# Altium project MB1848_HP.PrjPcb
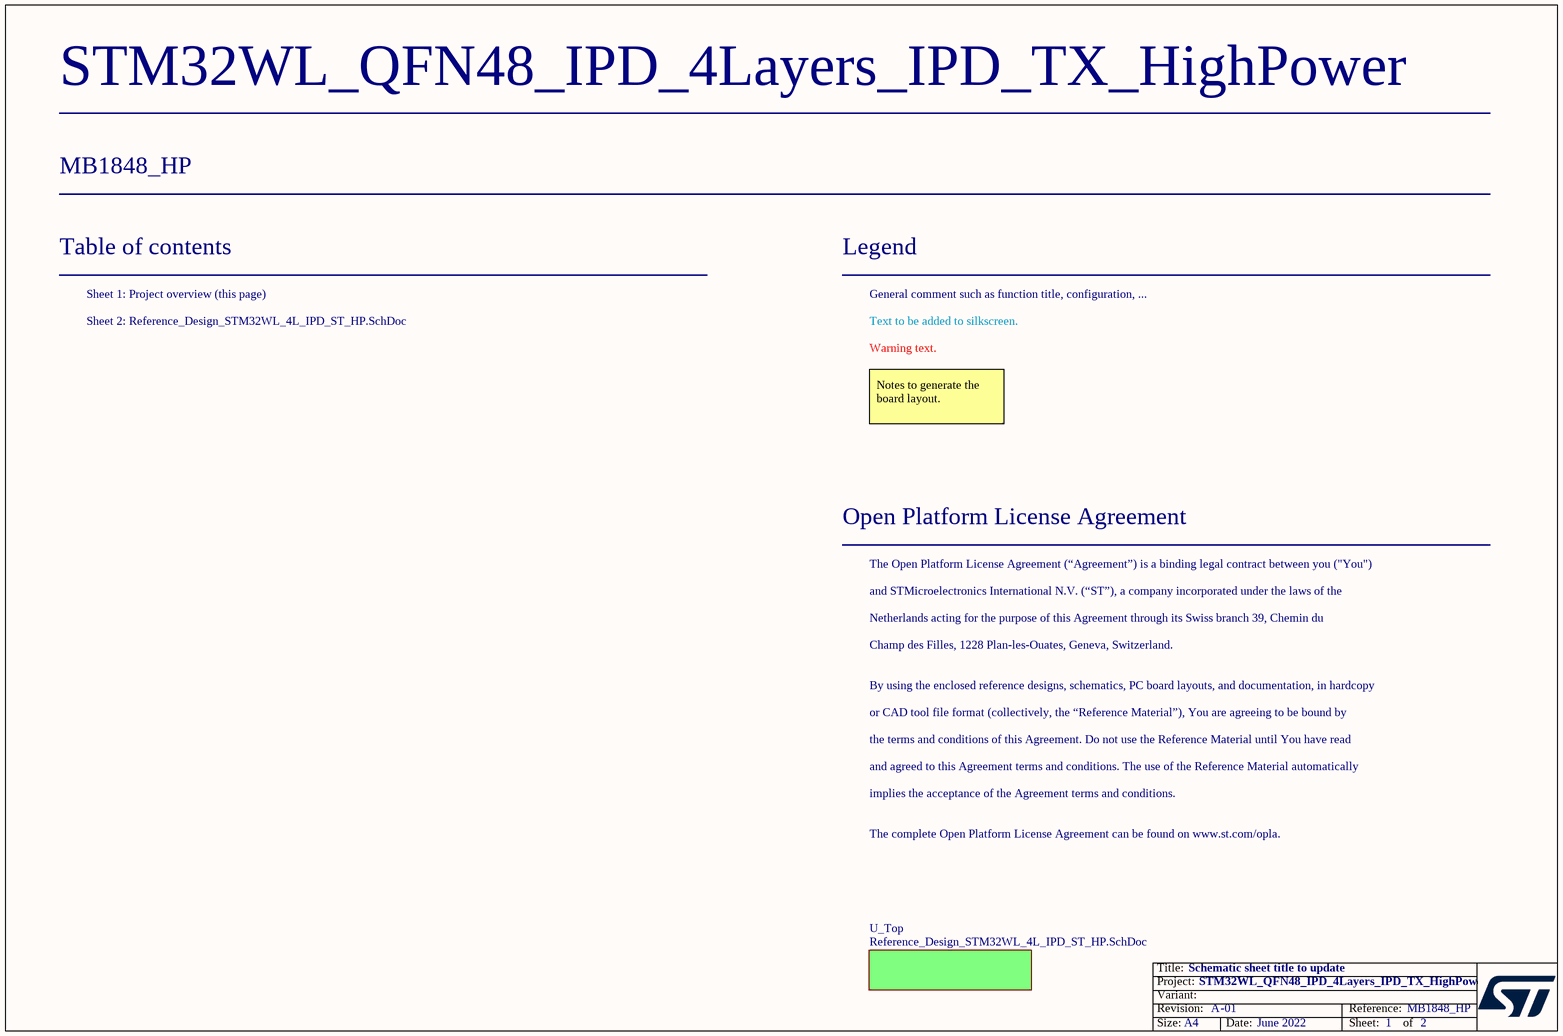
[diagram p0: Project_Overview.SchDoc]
Board_Assembly_Revision: 01; Board_Document_Date: June 2022; Board_Name: STM32WL_QFN48_IPD_4Layers_IPD_TX_HighPower; Board_PCB_Revision: A; Board_Reference: MB1848_HP
2 sheets, 123 parts. Net scope: flat (ports and power ports of the same name join across sheets).
Board file: MB1848_HP.PcbDoc
Sheets:
  Project_Overview.SchDoc
    U_Top = Reference_Design_STM32WL_4L_IPD_ST_HP.SchDoc

## Sheet Project_Overview.SchDoc: Schematic sheet title to update
size A4; Date: Not used; ApprovedBy: Not used; CheckedBy: Not used; Author: Not used; CompanyName: STMicroelectronics; DrawnBy: Not used; Engineer: Not used; Organization: Not used; Address1: Not used; Address2: Not used; Address3: Not used; Address4: Not used; DocumentNumber: Not used; Revision: Not used; SheetNumber: 1; SheetTotal: 2

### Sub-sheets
U_Top = Reference_Design_STM32WL_4L_IPD_ST_HP.SchDoc: no entries

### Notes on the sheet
- Table of contents
- Sheet 1: Project overview (this page)
- Legend
- General comment such as function title, configuration, ...
- Sheet 2: Reference_Design_STM32WL_4L_IPD_ST_HP.SchDoc
- Text to be added to silkscreen.
- Warning text.
- Notes to generate the board layout.
- Open Platform License Agreement
- The Open Platform License Agreement (“Agreement”) is a binding legal contract between you ("You")
- and STMicroelectronics International N.V. (“ST”), a company incorporated under the laws of the
- Netherlands acting for the purpose of this Agreement through its Swiss branch 39, Chemin du
- Champ des Filles, 1228 Plan-les-Ouates, Geneva, Switzerland.
- By using the enclosed reference designs, schematics, PC board layouts, and documentation, in hardcopy
- or CAD tool file format (collectively, the “Reference Material”), You are agreeing to be bound by
- the terms and conditions of this Agreement. Do not use the Reference Material until You have read
- and agreed to this Agreement terms and conditions. The use of the Reference Material automatically
- implies the acceptance of the Agreement terms and conditions.
- The complete Open Platform License Agreement can be found on www.st.com/opla.

## Sheet Reference_Design_STM32WL_4L_IPD_ST_HP.SchDoc: Schematic sheet title to update
size A3; Date: Not used; ApprovedBy: Not used; CheckedBy: Not used; Author: Not used; CompanyName: STMicroelectronics; DrawnBy: Not used; Engineer: Not used; Organization: Not used; Address1: Not used; Address2: Not used; Address3: Not used; Address4: Not used; DocumentNumber: Not used; Revision: Not used; SheetNumber: 2; SheetTotal: 2
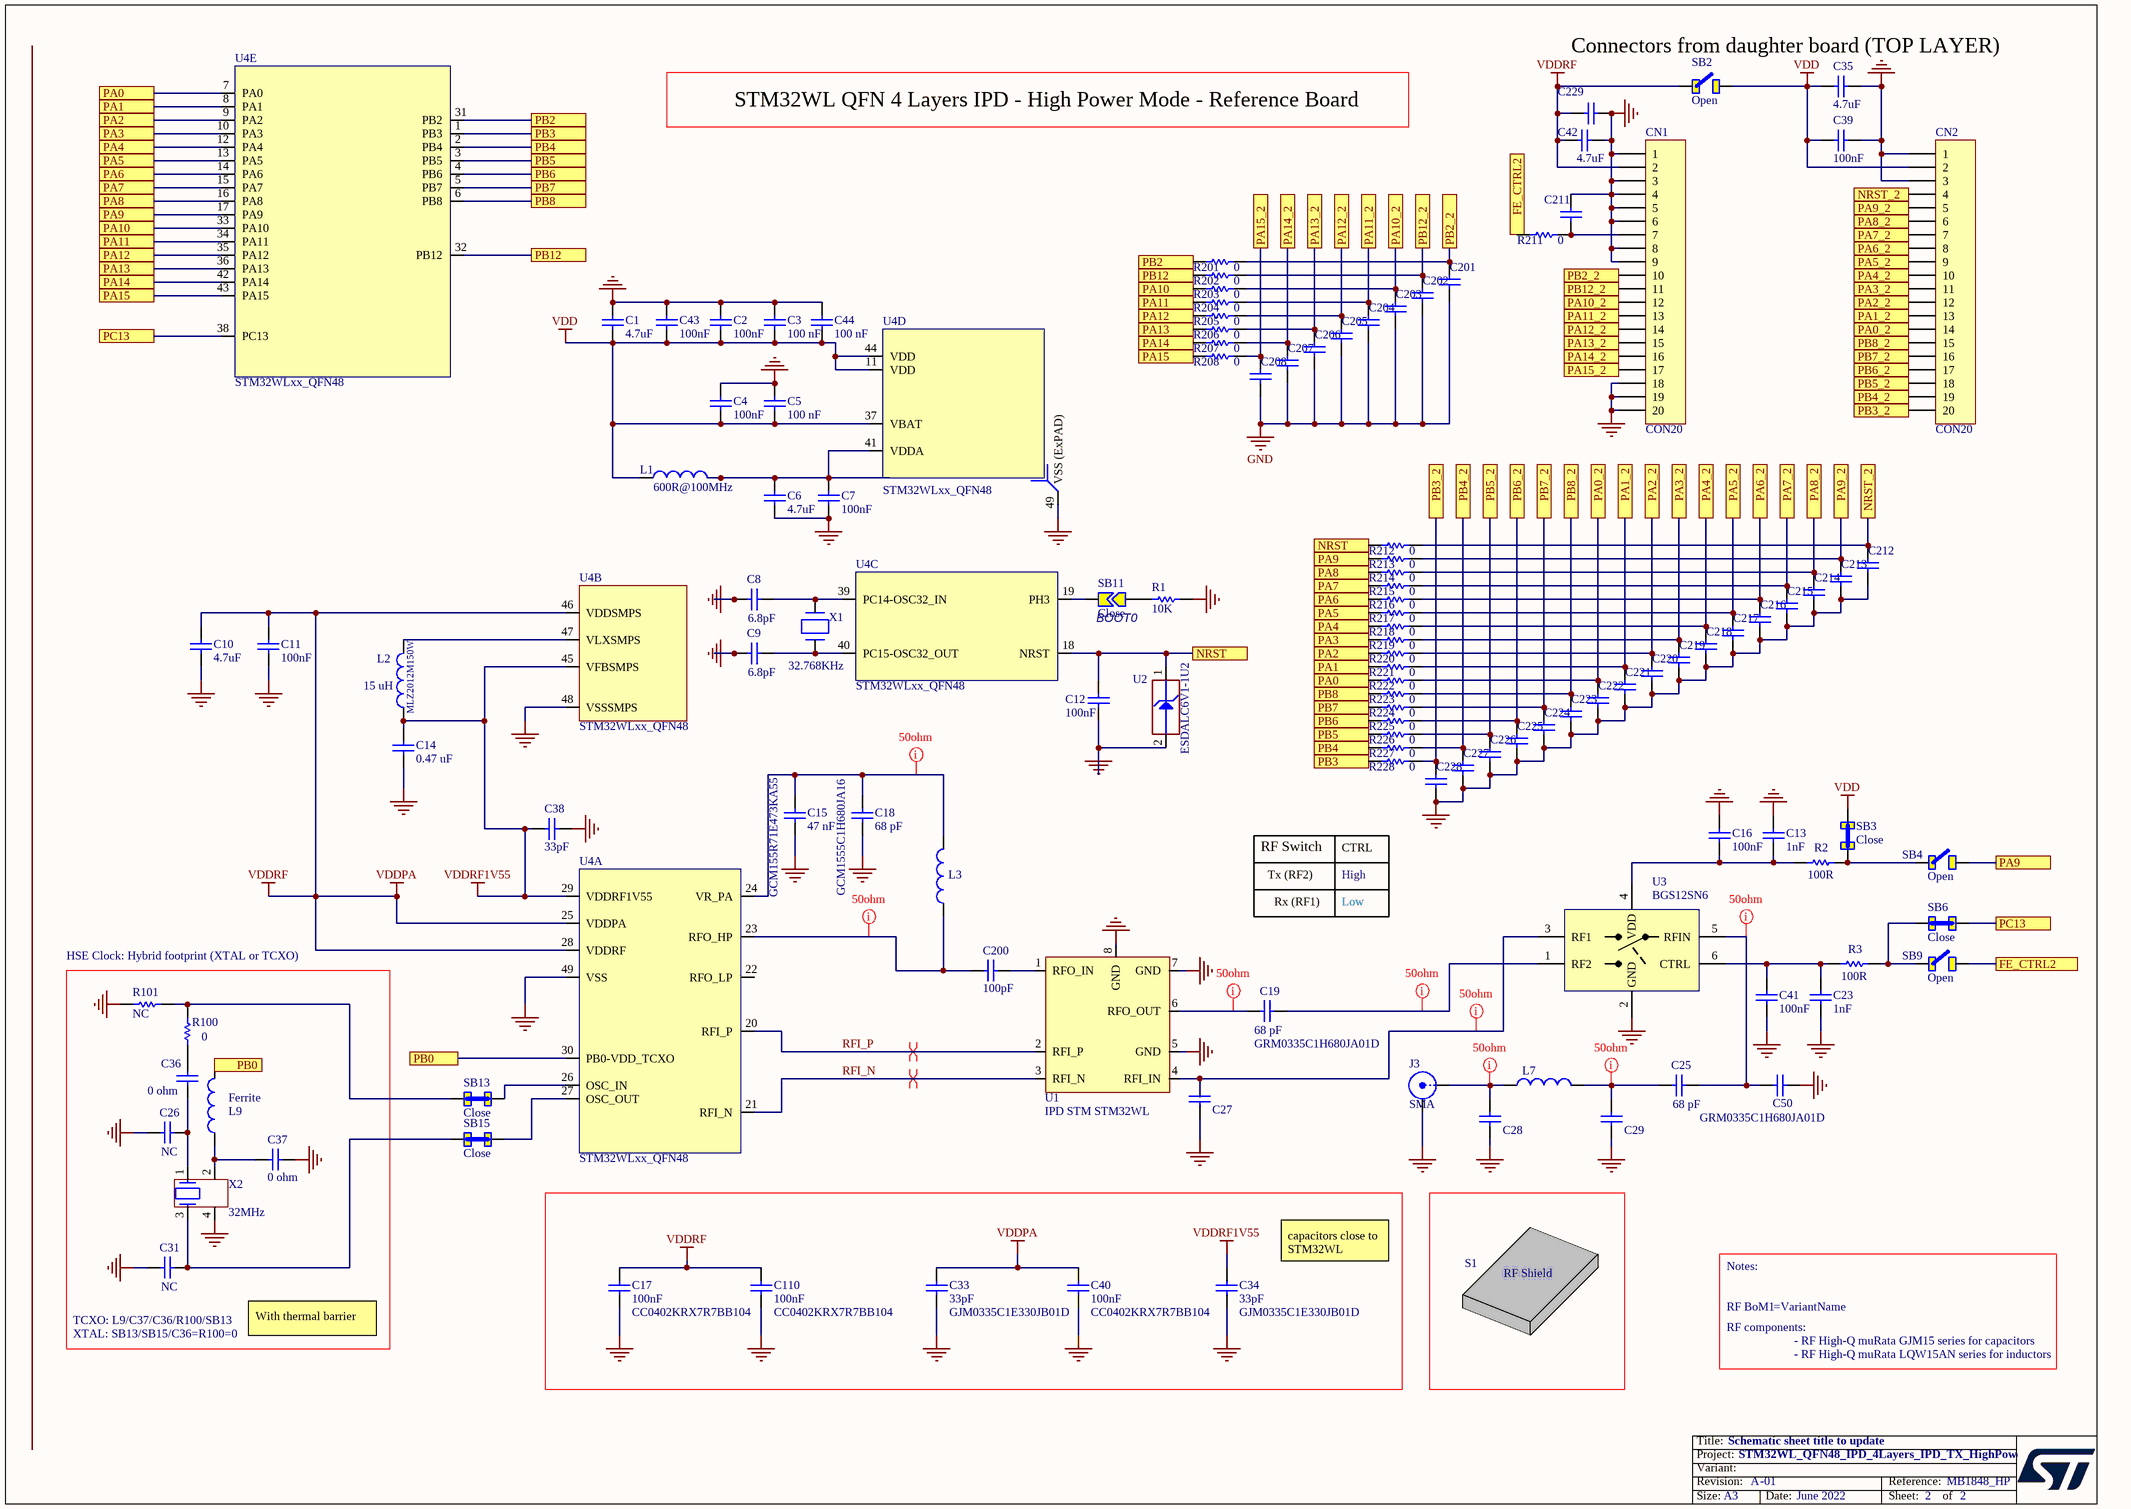
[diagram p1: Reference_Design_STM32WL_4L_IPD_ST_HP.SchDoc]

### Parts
C1  value 4.7uF  [CAPC1608X09N]
C2  value 100nF  [CAPC1005X06N]
C3  value 100 nF  [0201]
C4  value 100nF  [CAPC1005X06N]
C5  value 100 nF  [0201]
C6  value 4.7uF  [CAPC1608X09N]
C7  value 100nF  [CAPC1005X06N]
C8  value 6.8pF  [0402]  (hidden comment: Capacitor)
C9  value 6.8pF  [0402]  (hidden comment: Capacitor)
C10  value 4.7uF  [CAPC1608X09N]
C11  value 100nF  [CAPC1005X06N]
C12  value 100nF  [0402]
C13  value 1nF  [0201]  (hidden comment: MCD-00198)
C14  value 0.47 uF  [CAPC1608X09N]
C15  value 47 nF  Manufacturer_Part_Number: GCM155R71E473KA55  [0402]
C16  value 100nF  [0201]  (hidden comment: MCD-00102)
C17  value 100nF  Manufacturer_Part_Number: CC0402KRX7R7BB104  [CAPC1005X06N]
C18  value 68 pF  Manufacturer_Part_Number: GCM1555C1H680JA16  [0402]
C19  value 68 pF  Manufacturer_Part_Number: GRM0335C1H680JA01D  [rlc_201_smd]  (hidden comment: RFCapacitor_201)
C23  value 1nF  [0201]  (hidden comment: MCD-00198)
C25  value 68 pF  Manufacturer_Part_Number: GRM0335C1H680JA01D  [rlc_201_smd]  (hidden comment: RFCapacitor_201)
C26  value NC  [0402]  (hidden comment: Capacitor)
C27  NC  [0201]  (value not drawn)
C28  RFCapacitor_201  [rlc_201_smd]  (value not drawn)
C29  RFCapacitor_201  [rlc_201_smd]  (value not drawn)
C31  value NC  [0402]  (hidden comment: Capacitor)
C33  value 33pF  Manufacturer_Part_Number: GJM0335C1E330JB01D  [0201]
C34  value 33pF  Manufacturer_Part_Number: GJM0335C1E330JB01D  [0201]
C35  value 4.7uF  [CAPC1608X09N]
C36  value 0 ohm  [0402]
C37  value 0 ohm  [0402]
C38  value 33pF  [0201]
C39  value 100nF  [CAPC1005X06N]
C40  value 100nF  Manufacturer_Part_Number: CC0402KRX7R7BB104  [CAPC1005X06N]
C41  value 100nF  [0201]  (hidden comment: MCD-00102)
C42  value 4.7uF  [CAPC1608X09N]
C43  value 100nF  [CAPC1005X06N]
C44  value 100 nF  [0201]
C50  RFCapacitor_201  [rlc_201_smd]  (value not drawn)
C110  value 100nF  Manufacturer_Part_Number: CC0402KRX7R7BB104  [CAPC1005X06N]
C200  value 100pF  [0201]  (hidden comment: MCD-00198)
C201  RFCapacitor_201  [rlc_201_smd]  (value not drawn)
C202  RFCapacitor_201  [rlc_201_smd]  (value not drawn)
C203  RFCapacitor_201  [rlc_201_smd]  (value not drawn)
C204  RFCapacitor_201  [rlc_201_smd]  (value not drawn)
C205  RFCapacitor_201  [rlc_201_smd]  (value not drawn)
C206  RFCapacitor_201  [rlc_201_smd]  (value not drawn)
C207  RFCapacitor_201  [rlc_201_smd]  (value not drawn)
C208  RFCapacitor_201  [rlc_201_smd]  (value not drawn)
C211  RFCapacitor_201  [rlc_201_smd]  (value not drawn)
C212  RFCapacitor_201  [rlc_201_smd]  (value not drawn)
C213  RFCapacitor_201  [rlc_201_smd]  (value not drawn)
C214  RFCapacitor_201  [rlc_201_smd]  (value not drawn)
C215  RFCapacitor_201  [rlc_201_smd]  (value not drawn)
C216  RFCapacitor_201  [rlc_201_smd]  (value not drawn)
C217  RFCapacitor_201  [rlc_201_smd]  (value not drawn)
C218  RFCapacitor_201  [rlc_201_smd]  (value not drawn)
C219  RFCapacitor_201  [rlc_201_smd]  (value not drawn)
C220  RFCapacitor_201  [rlc_201_smd]  (value not drawn)
C221  RFCapacitor_201  [rlc_201_smd]  (value not drawn)
C222  RFCapacitor_201  [rlc_201_smd]  (value not drawn)
C223  RFCapacitor_201  [rlc_201_smd]  (value not drawn)
C224  RFCapacitor_201  [rlc_201_smd]  (value not drawn)
C225  RFCapacitor_201  [rlc_201_smd]  (value not drawn)
C226  RFCapacitor_201  [rlc_201_smd]  (value not drawn)
C227  RFCapacitor_201  [rlc_201_smd]  (value not drawn)
C228  RFCapacitor_201  [rlc_201_smd]  (value not drawn)
C229  RFCapacitor_201  [rlc_201_smd]  (value not drawn)
CN1  CON20  [CO_SAMTEC_TSW-120-07-x-S]
CN2  CON20  [CO_SAMTEC_TSW-120-07-x-S]
J3  SMA  [SMA_AMPHENOL_50ohms_Edge_PCB]
L1  value 600R@100MHz  [INDC1608X95N]
L2  value 15 uH  Manufacturer_Part_Number: MLZ2012M150W  [INDC2012X13N]
L3  MCD-01330  [IND_MURATA_LQW15A]  (value not drawn)
L7  Ferrite  [rlc_201_smd]  (value not drawn)
L9  Ferrite  [IND_MURATA_LQW15A]
R1  value 10K  [RESC1608X05N]
R2  value 100R  [0201]  (hidden comment: MCD-00119)
R3  value 100R  [0201]  (hidden comment: MCD-00119)
R100  value 0  [R0402]  (hidden comment: Resistor)
R101  value NC  [R0402]  (hidden comment: Resistor)
R201  value 0  [0201]  (hidden comment: MCD-00119)
R202  value 0  [0201]  (hidden comment: MCD-00119)
R203  value 0  [0201]  (hidden comment: MCD-00119)
R204  value 0  [0201]  (hidden comment: MCD-00119)
R205  value 0  [0201]  (hidden comment: MCD-00119)
R206  value 0  [0201]  (hidden comment: MCD-00119)
R207  value 0  [0201]  (hidden comment: MCD-00119)
R208  value 0  [0201]  (hidden comment: MCD-00119)
R211  value 0  [0201]  (hidden comment: MCD-00119)
R212  value 0  [0201]  (hidden comment: MCD-00119)
R213  value 0  [0201]  (hidden comment: MCD-00119)
R214  value 0  [0201]  (hidden comment: MCD-00119)
R215  value 0  [0201]  (hidden comment: MCD-00119)
R216  value 0  [0201]  (hidden comment: MCD-00119)
R217  value 0  [0201]  (hidden comment: MCD-00119)
R218  value 0  [0201]  (hidden comment: MCD-00119)
R219  value 0  [0201]  (hidden comment: MCD-00119)
R220  value 0  [0201]  (hidden comment: MCD-00119)
R221  value 0  [0201]  (hidden comment: MCD-00119)
R222  value 0  [0201]  (hidden comment: MCD-00119)
R223  value 0  [0201]  (hidden comment: MCD-00119)
R224  value 0  [0201]  (hidden comment: MCD-00119)
R225  value 0  [0201]  (hidden comment: MCD-00119)
R226  value 0  [0201]  (hidden comment: MCD-00119)
R227  value 0  [0201]  (hidden comment: MCD-00119)
R228  value 0  [0201]  (hidden comment: MCD-00119)
RF_BoM1  RF-BOM  (value not drawn)  (mechanical)
S1  RF-Shield  (value not drawn)  (mechanical)
SB2  Open  [SB_0402]
SB3  Close  [0201]
SB4  Open  [0201]
SB6  Close  [0201]
SB9  Open  [0201]
SB11  Close  [GC_0402]
SB13  Close  [SB_0402]
SB15  Close  [SB_0402]
U1  IPD STM STM32WL  [IPD STM]
U2  Manufacturer_Part_Number: ESDALC6V1-1U2  [DIOM0603X03N]
U3  BGS12SN6  [TSNP-6-2]
U4  STM32WLxx_QFN48  [STM32WLxx_QFN48]  (parts A,B,C,D,E of 5)
X1  value 32.768KHz  [OSC_NDK_NX2012SA]  (hidden comment: XTAL_2_PINS)
X2  value 32MHz  [OSC_NDK_NX2016SA]

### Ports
FE_CTRL2, NRST, NRST_2, PA0, PA0_2, PA1, PA1_2, PA2, PA2_2, PA3, PA3_2, PA4, PA4_2, PA5, PA5_2, PA6, PA6_2, PA7, PA7_2, PA8, PA8_2, PA9, PA9_2, PA10, PA10_2, PA11, PA11_2, PA12, PA12_2, PA13, PA13_2, PA14, PA14_2, PA15, PA15_2, PB0, PB2, PB2_2, PB3, PB3_2, PB4, PB4_2, PB5, PB5_2, PB6, PB6_2, PB7, PB7_2, PB8, PB8_2, PB12, PB12_2, PC13

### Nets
GND: C1.1 C2.1 C3.1 C4.1 C5.1 C6.2 C7.2 C8.2 C9.2 C10.2 C11.2 C12.2 C13.1 C14.2 C15.2 C16.1 C17.2 C18.1 C23.1 C26.2 C27.1 C28.1 C29.1 C31.2 C33.1 C34.1 C35.1 C37.1 C38.2 C39.2 C40.2 C41.2 C42.2 C43.1 C44.1 C50.1 C110.2 C201.2 C202.2 C203.2 C204.2 C205.2 C206.2 C207.2 C208.2 C211.1 C212.2 C213.2 C214.2 C215.2 C216.2 C217.2 C218.2 C219.2 C220.2 C221.2 C222.2 C223.2 C224.2 C225.2 C226.2 C227.2 C228.2 C229.2 CN1.1 CN1.3 CN1.4 CN1.5 CN1.6 CN1.8 CN1.9 CN1.18 CN1.19 CN1.20 CN2.1 CN2.3 J3.2(GND) R1.1 R101.2 U1.5(GND) U1.7(GND) U1.8(GND) U2.2(GND) U3.2(GND) U4.48(VSSSMPS) U4.49(VSS_(ExPAD)) X2.4
VDD: C1.2 C2.2 C3.2 C4.2 C5.2 C35.2 C39.1 C43.2 C44.2 CN2.2 L1.1 SB2.1 SB3.1 U4.11(VDD) U4.37(VBAT) U4.44(VDD)
VDDPA: C10.1 C11.1 C17.1 C33.2 C40.1 C42.1 C110.1 C229.1 CN1.2 SB2.2 U4.25(VDDPA) U4.28(VDDRF) U4.46(VDDSMPS)  [also labelled VDDRF]
VDDRF1V55: C14.1 C34.2 C38.1 L2.1 U4.29(VDDRF1V55) U4.45(VFBSMPS)
RFI_N: U1.3(RFI_N) U4.21(RFI_N)
RFI_P: U1.2(RFI_P) U4.20(RFI_P)
NetC6_1: C6.1 C7.1 L1.2 U4.41(VDDA)
NetC8_1: C8.1 U4.39(PC14-OSC32_IN) X1.2(X2)
NetC9_1: C9.1 U4.40(PC15-OSC32_OUT) X1.1(X1)
NetC12_1: C12.1 R212.1 U2.1(IO1) U4.18(NRST) ; port NRST
NetC13_2: C13.2 C16.2 R2.1 U3.4(VDD)
NetC15_1: C15.1 C18.2 L3.1 U4.24(VR_PA)
NetC19_1: C19.1 U3.1(RF2)
NetC19_2: C19.2 U1.6(RFO_OUT)
NetC23_2: C23.2 C41.1 R3.1 U3.6(CTRL)
NetC25_1: C25.1 C50.2 U3.5(RFIN)
NetC25_2: C25.2 C29.2 L7.1
NetC26_1: C26.1 C36.2 X2.1
NetC27_2: C27.2 U1.4(RFI_IN) U3.3(RF1)
NetC28_2: C28.2 J3.1(Signal) L7.2
NetC31_1: C31.1 SB15.2 X2.3
NetC36_1: C36.1 R100.2
NetC37_2: C37.2 L9.1 X2.2
NetC200_1: C200.1 U1.1(RFO_IN)
NetC200_2: C200.2 L3.2 U4.23(RFO_HP)
NetC201_1: C201.1 CN1.10 R201.2 ; port PB2_2
NetC202_1: C202.1 CN1.11 R202.2 ; port PB12_2
NetC203_1: C203.1 CN1.12 R203.2 ; port PA10_2
NetC204_1: C204.1 CN1.13 R204.2 ; port PA11_2
NetC205_1: C205.1 CN1.14 R205.2 ; port PA12_2
NetC206_1: C206.1 CN1.15 R206.2 ; port PA13_2
NetC207_1: C207.1 CN1.16 R207.2 ; port PA14_2
NetC208_1: C208.1 CN1.17 R208.2 ; port PA15_2
NetC211_2: C211.2 CN1.7 R211.2
NetC212_1: C212.1 CN2.4 R212.2 ; port NRST_2
NetC213_1: C213.1 CN2.5 R213.2 ; port PA9_2
NetC214_1: C214.1 CN2.6 R214.2 ; port PA8_2
NetC215_1: C215.1 CN2.7 R215.2 ; port PA7_2
NetC216_1: C216.1 CN2.8 R216.2 ; port PA6_2
NetC217_1: C217.1 CN2.9 R217.2 ; port PA5_2
NetC218_1: C218.1 CN2.10 R218.2 ; port PA4_2
NetC219_1: C219.1 CN2.11 R219.2 ; port PA3_2
NetC220_1: C220.1 CN2.12 R220.2 ; port PA2_2
NetC221_1: C221.1 CN2.13 R221.2 ; port PA1_2
NetC222_1: C222.1 CN2.14 R222.2 ; port PA0_2
NetC223_1: C223.1 CN2.15 R223.2 ; port PB8_2
NetC224_1: C224.1 CN2.16 R224.2 ; port PB7_2
NetC225_1: C225.1 CN2.17 R225.2 ; port PB6_2
NetC226_1: C226.1 CN2.18 R226.2 ; port PB5_2
NetC227_1: C227.1 CN2.19 R227.2 ; port PB4_2
NetC228_1: C228.1 CN2.20 R228.2 ; port PB3_2
NetL2_2: L2.2 U4.47(VLXSMPS)
NetL9_2: L9.2 U4.30(PB0-VDD_TCXO) ; port PB0
NetR1_2: R1.2 SB11.1
NetR2_2: R2.2 SB3.2 SB4.2
NetR3_2: R3.2 SB6.2 SB9.2
NetR100_1: R100.1 R101.1 SB13.2
NetR201_1: R201.1 U4.31(PB2) ; port PB2
NetR202_1: R202.1 U4.32(PB12) ; port PB12
NetR203_1: R203.1 U4.33(PA10) ; port PA10
NetR204_1: R204.1 U4.34(PA11) ; port PA11
NetR205_1: R205.1 U4.35(PA12) ; port PA12
NetR206_1: R206.1 U4.36(PA13) ; port PA13
NetR207_1: R207.1 U4.42(PA14) ; port PA14
NetR208_1: R208.1 U4.43(PA15) ; port PA15
NetR211_1: R211.1 SB9.1 ; port FE_CTRL2
NetR213_1: R213.1 SB4.1 U4.17(PA9) ; port PA9
NetR214_1: R214.1 U4.16(PA8) ; port PA8
NetR215_1: R215.1 U4.15(PA7) ; port PA7
NetR216_1: R216.1 U4.14(PA6) ; port PA6
NetR217_1: R217.1 U4.13(PA5) ; port PA5
NetR218_1: R218.1 U4.12(PA4) ; port PA4
NetR219_1: R219.1 U4.10(PA3) ; port PA3
NetR220_1: R220.1 U4.9(PA2) ; port PA2
NetR221_1: R221.1 U4.8(PA1) ; port PA1
NetR222_1: R222.1 U4.7(PA0) ; port PA0
NetR223_1: R223.1 U4.6(PB8) ; port PB8
NetR224_1: R224.1 U4.5(PB7) ; port PB7
NetR225_1: R225.1 U4.4(PB6) ; port PB6
NetR226_1: R226.1 U4.3(PB5) ; port PB5
NetR227_1: R227.1 U4.2(PB4) ; port PB4
NetR228_1: R228.1 U4.1(PB3) ; port PB3
NetSB6_1: SB6.1 U4.38(PC13) ; port PC13
NetSB11_2: SB11.2 U4.19(PH3)
NetSB13_1: SB13.1 U4.26(OSC_IN)
NetSB15_1: SB15.1 U4.27(OSC_OUT)

Not connected (* = marked no-connect by the designer): U4 22(RFO_LP)

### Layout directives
net class 50ohm: NetC15_1, NetC19_1, NetC19_2, NetC25_1, NetC25_2, NetC27_2, NetC28_2, NetC200_2
differential pair: RFI_N, RFI_P

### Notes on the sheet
- STM32WL QFN 4 Layers IPD - High Power Mode - Reference Board
- Connectors from daughter board (TOP LAYER)
- BOOT0
- RF Switch
- CTRL
- Tx (RF2)
- Rx (RF1)
- Low
- High
- HSE Clock: Hybrid footprint (XTAL or TCXO)
- capacitors close to STM32WL
- (near C31) TCXO: L9/C37/C36/R100/SB13
- Notes:
- XTAL: SB13/SB15/C36=R100=0
- With thermal barrier
- RF components:
- (near RF_BoM1) - RF High-Q muRata GJM15 series for capacitors
- (near RF_BoM1) - RF High-Q muRata LQW15AN series for inductors

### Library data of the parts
C1 C6 C10 C35 C42 = MCD-00009: Capacitor, MLCC, 4.7uF, 16V, X5R, 10%, 0603, T=0.8mm; Manufacturer_Part_Number: CC0603KRX5R7BB475; Manufacturer: YAGEO
C2 C4 C7 C11 C12 C39 C43 = MCD-00102: Capacitor, MLCC, 100nF, 16V, X7R, 10%, 0402, T=0,5mm; Manufacturer_Part_Number: CC0402KRX7R7BB104; Manufacturer: YAGEO
C3 C5 C44 = MCD-00102: Multilayer Ceramic Capacitors MLCC - SMD/SMT 0201 25VDC 0.1uF 10% X5R 0.3mm; Manufacturer_Part_Number: C0603X5R1E104K030BB; Manufacturer: TDK
C8 C9 = MCD-00003: Capacitor, MLCC, 6.8pF, 50V, NPO, +-0.1pF, 0402, T=0.5mm; Manufacturer_Part_Number: GRM1555C1H6R8BA01; Manufacturer: MURATA
C13 C23 = MCD-00198: Multilayer ceramic capacitors X7R ±10%, 50V; Manufacturer_Part_Number: GRM033R71H102KA12D; Manufacturer: MURATA
C14 = MCD-00009: Capacitor, MLCC, 4.7 uF, 16V, X5R, 10%, 0603, T=0.8mm; Manufacturer_Part_Number: CC0603KRX5R7BB474; Manufacturer: YAGEO
C15 = MCD-01123: Capacitor, MLCC,47nF, 16V, X7R, 10%, 0402, T=0.5mm; Manufacturer: MURATA
C16 C41 = MCD-00102: Multilayer ceramic capacitors X5R ±10%, 10V; Manufacturer_Part_Number: GRM033R61A104KE15D; Manufacturer: MURATA
C17 C40 C110 = MCD-00102: Capacitor, MLCC, 100nF, 16V, X7R, 10%, 0402, T=0,5mm; Manufacturer: YAGEO
C18 = MCD-01123: Capacitor, MLCC,68pF, 50V, C0G, 1%, 0402, T=0.5mm; Manufacturer: MURATA
C19 C25 = RFCapacitor_201: Multilayer ceramic capacitors COG ±5%, 50V; Manufacturer: MURATA
C26 C31 = MCD-00003: Not connected
C27 = RFCapacitor_201: RF Capacitor High-Q, 0201
C28 C29 C50 C201-C208 C211-C229 = RFCapacitor_201: RF Capacitor High-Q, 0201; Value: NC
C33 C34 = MCD-00277: Multilayer Ceramic Capacitors MLCC - SMD/SMT 0201 33pF 25volts C0G 5%; Manufacturer: MURATA
C36 C37 = MCD-00277: Capacitor, MLCC, 33pF, 50V, NPO, 2%, 0402, T=0,5mm; Manufacturer_Part_Number: RCS04020000Z0ED; Manufacturer: Vishay / Dale
C38 = MCD-01123: Multilayer Ceramic Capacitors MLCC - SMD/SMT 0201 33pF 25volts C0G 5%; Manufacturer_Part_Number: GJM0335C1E330JB01D; Manufacturer: MURATA
C200 = MCD-00198: Multilayer ceramic capacitors COG +/-5%, 50V; Manufacturer_Part_Number: GRM033R71H102KA12D; Manufacturer: MURATA
CN1 CN2 = CON20: Connector right-angle, pitch 2.54mm, 20 contacts; Manufacturer: SAMTEC; Manufacturer_Part_Number: TSW-120-07-L-S
J3 = SMA: SMA Straight Connector; Manufacturer: Johnson / Cinch Connectivity Solutions; Manufacturer_Part_Number: 142-0701-841
L1 = MCD-00047: SMD Chip ferrite bead, 600R@100MHz +/-25%, 350mA, 500mohm DC, 0603, T=0.8mm; Manufacturer_Part_Number: BK1608HS601-T; Manufacturer: Taiyo Yuden
L2 = MCD-01433: MLZ2012 Multilayer Shielded Inductor 15 uH, ±5%; Manufacturer: TDK
L3 = MCD-01330: Inductor, 47nH, +-0.1nH, 140mA, 0402; Value: NC
L7 = RFInductor_201: Thick Film Resistor ±5%, 1/20W; Manufacturer_Part_Number: CRCW02010000Z0ED; Manufacturer: Vishay/Dale; Value: 0R
L9 = MCD-01330: Not connected; Part_Type: Ferrite bead; Value: NC; Provided_By: SUBCO; Initial_Board_Reference: MB1402
R1 = MCD-00220: Resistor,10K,0603,1%,1/10W; Manufacturer_Part_Number: RC0603FR-0710KL; Manufacturer: YAGEO
R2 R3 R201-R208 R211-R228 = MCD-00119: Thick Film Resistors - SMD 1/20watt 100ohms 5% 200ppm; Manufacturer_Part_Number: CRCW0201100RJNED; Manufacturer: Vishay / Dale
R100 = MCD-00052: Resistor,0R,0402,5%,1/16W; Manufacturer_Part_Number: RC0402JR-070RL; Manufacturer: YAGEO; Provided_By: SUBCO; Initial_Board_Reference: MB1274
R101 = MCD-00052: Not connected; Manufacturer: YAGEO; Provided_By: SUBCO; Initial_Board_Reference: MB1274
S1 = RF-Shield: RF Shield Frame + Cover without apertures; Manufacturer: Masach Tech; Manufacturer_Part_Number: MS409-10
SB2 SB4 SB9 = SB_Open: Solder Bridge Open [0402] (Unpopulated)
SB3 SB6 = SB_0Ohm: Thick Film Resistors - SMD 1/20watt ZEROohm Jumper; Manufacturer: Vishay / Dale; Manufacturer_Part_Number: CRCW02010000Z0ED; VALUE: 0
SB11 = Strap2: Solder Jumper - Close; Manufacturer: Vishay / Dale; Manufacturer_Part_Number: RCS04020000Z0ED
SB13 SB15 = SB_0Ohm: Solder Bridge 0R [0402] (Populated with 0 Ohm); Manufacturer: Vishay / Dale; Manufacturer_Part_Number: RCS04020000Z0ED; VALUE: 0
U1 = IPD ST STM32WL: Manufacturer: STMICROELECTRONICS
U2 = MCD-00170: ESD protection 6V1; Manufacturer: STMICROELECTRONICS
U3 = BGS12SN6: DC switch - Ultra-Low  SPDT analog switch; Manufacturer: INFINEON
U4 = STM32WLxx_QFN48: STM32WL ARM MCU Multiprotocol LPWAN 32-bit Arm Cortex-M4 MCUs LoRa (G)FSK-MSK BPSK; Manufacturer_Part_Number: STM32WLE5CC; Manufacturer: STMicroelectronics
X1 = MCD-01479: Crystal 32.768kHz, 6pF, -+20PPM, R=80K, SMD; Manufacturer_Part_Number: NX2012SA 32.768KHz EXS00A-MU00527; Manufacturer: NDK
X2 = MCD-01446: Crystal 32 MHz, 8pF, -+10 PPM, R=60Ω, SMD; Manufacturer_Part_Number: NX2016SA 32MHz EXS00A-CS06465; Manufacturer: NDK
